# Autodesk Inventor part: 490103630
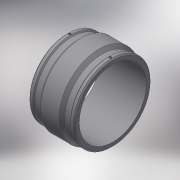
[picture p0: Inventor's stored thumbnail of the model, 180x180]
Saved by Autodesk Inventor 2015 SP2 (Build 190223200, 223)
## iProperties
Created: 2017-06
Part Number: 490103630
Material: Generic
Description: PLASSON COUPLER 630
Document SubType Name: Modeling
Designer: KIM
Mass: 16398.8 g
Surface Area: 10528.4 cm^2
Volume: 16398.8 cm^3
Density: 1 g/cm^3
Appearance: Default
Author: KIM
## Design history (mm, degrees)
derived "490103.ipt"
feature "Solid1::490103.ipt"
tag "TaggingFeature1"
body "Solid1"
other parameters: "d13" = 418, "d15" = 209, "d16" = 209, "d22" = 712, "d23" = 759, "d24" = 690.64, "d25" = 135 deg, "d26" = 167.2, "d27" = 135 deg, "d29" = 356, "d35" = 15, "d39" = 0, "d40" = 4, "d41" = 14, "d42" = 0, "d43" = 135 deg, "d44" = 45.98, "d46" = 6, "d47" = 0, "L_" = 418, "L_1" = 209, "D_" = 759, "A_" = 356, "d_2" = 12
